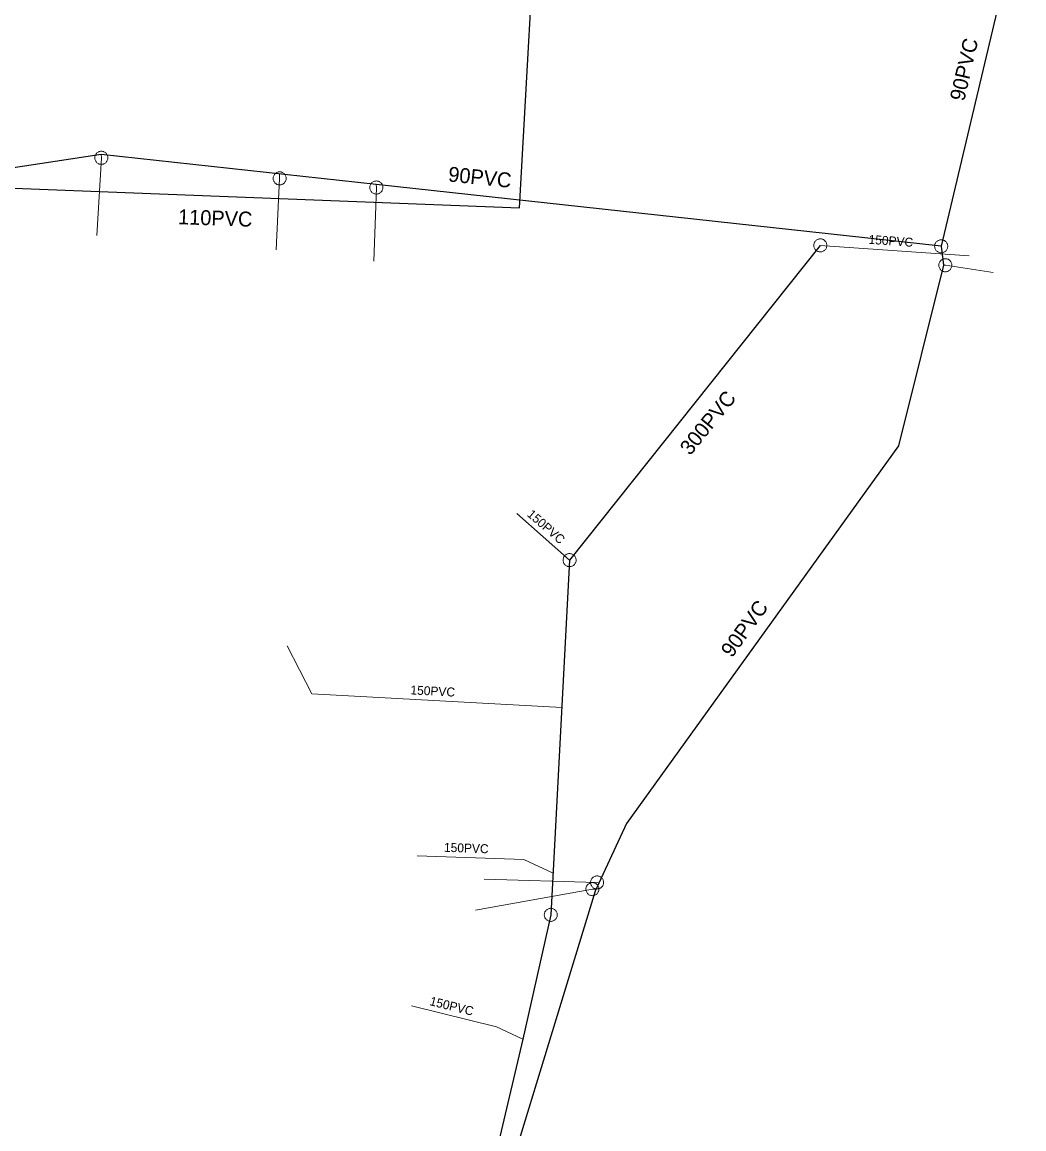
# Model space of a CAD drawing. Extents: x -741806 to -738704, y -1059275 to -1055387.
# Drawn here: x -740667.8 to -740600.7, y -1057651.1 to -1057576.9 of the extents above; entities that cross this region are included whole.
import ezdxf

# ---------------------------------------------------------------- set-up
doc = ezdxf.new("R2010")
doc.units = 0
doc.header["$LTSCALE"] = 0.4
for name, color, linetype, lineweight in [('2', 7, 'Continuous', 25), ('21', 7, 'Continuous', 13), ('3', 7, 'Continuous', 13), ('51', 7, 'Continuous', 13), ('52', 7, 'Continuous', 25), ('56', 7, 'Continuous', 13)]:
    doc.layers.add(name, color=color, linetype=linetype, lineweight=lineweight)
for name, color, linetype in [('5', 7, 'Continuous'), ('53', 7, 'Continuous'), ('55', 7, 'Continuous')]:
    doc.layers.add(name, color=color, linetype=linetype)

msp = doc.modelspace()

# ---------------------------------------------------------------- linework, layer by layer
at = {"layer": '2'}
for points in [[(-740702.59, -1057629.575), (-740677.195, -1057630.344), (-740674.756, -1057596.152), (-740674.105, -1057587.855), (-740634.449, -1057589.387), (-740633.142, -1057565.869)], [(-740614.3, -1057591.909), (-740631.1, -1057613), (-740632.359, -1057636.77), (-740634.23, -1057645.105), (-740637.395, -1057658.567), (-740638.78, -1057664.69), (-740636.789, -1057669.73), (-740646.329, -1057707.36), (-740651.609, -1057710.669)]]:
    msp.add_lwpolyline(points, dxfattribs=at)
at = {"layer": '21'}
for points in [[(-740662.486, -1057585.823), (-740662.48, -1057586.04), (-740662.782, -1057591.249)], [(-740650.542, -1057587.127), (-740650.53, -1057587.419), (-740650.767, -1057592.213)], [(-740644.067, -1057587.834), (-740644.05, -1057588.03), (-740644.224, -1057592.965)], [(-740606.041, -1057593.243), (-740605.92, -1057593.24), (-740602.725, -1057593.729)], [(-740629.138, -1057634.655), (-740629.26, -1057634.6), (-740636.829, -1057634.37)], [(-740629.339, -1057635.057), (-740629.57, -1057635.05), (-740637.417, -1057636.446)]]:
    msp.add_lwpolyline(points, dxfattribs=at)
at = {"layer": '3'}
for points in [[(-740614.736, -1057591.878), (-740614.737, -1057591.923), (-740614.733, -1057591.968), (-740614.724, -1057592.014), (-740614.711, -1057592.057), (-740614.693, -1057592.099), (-740614.67, -1057592.14), (-740614.644, -1057592.177), (-740614.614, -1057592.212), (-740614.58, -1057592.242), (-740614.544, -1057592.27), (-740614.505, -1057592.294), (-740614.463, -1057592.314), (-740614.42, -1057592.328), (-740614.376, -1057592.339), (-740614.33, -1057592.344), (-740614.284, -1057592.345), (-740614.238, -1057592.34), (-740614.194, -1057592.332), (-740614.15, -1057592.318), (-740614.107, -1057592.3), (-740614.068, -1057592.278), (-740614.031, -1057592.252), (-740613.995, -1057592.222), (-740613.964, -1057592.189), (-740613.936, -1057592.152), (-740613.914, -1057592.112), (-740613.894, -1057592.072), (-740613.879, -1057592.027), (-740613.869, -1057591.983), (-740613.863, -1057591.937), (-740613.862, -1057591.892), (-740613.866, -1057591.847), (-740613.875, -1057591.801), (-740613.889, -1057591.757), (-740613.906, -1057591.716), (-740613.928, -1057591.675), (-740613.955, -1057591.638), (-740613.986, -1057591.603), (-740614.019, -1057591.573), (-740614.055, -1057591.545), (-740614.094, -1057591.521), (-740614.136, -1057591.501), (-740614.179, -1057591.486), (-740614.223, -1057591.476), (-740614.269, -1057591.471), (-740614.315, -1057591.47), (-740614.36, -1057591.474), (-740614.405, -1057591.483), (-740614.449, -1057591.497), (-740614.492, -1057591.515), (-740614.531, -1057591.537), (-740614.569, -1057591.562), (-740614.603, -1057591.593), (-740614.635, -1057591.626), (-740614.662, -1057591.663), (-740614.686, -1057591.703), (-740614.705, -1057591.743), (-740614.72, -1057591.788), (-740614.73, -1057591.832), (-740614.736, -1057591.877)], [(-740630.771, -1057613.29), (-740630.744, -1057613.254), (-740630.719, -1057613.215), (-740630.699, -1057613.174), (-740630.683, -1057613.132), (-740630.671, -1057613.087), (-740630.664, -1057613.041), (-740630.663, -1057612.996), (-740630.665, -1057612.95), (-740630.674, -1057612.905), (-740630.686, -1057612.861), (-740630.702, -1057612.818), (-740630.723, -1057612.777), (-740630.749, -1057612.74), (-740630.778, -1057612.704), (-740630.811, -1057612.672), (-740630.847, -1057612.643), (-740630.886, -1057612.619), (-740630.926, -1057612.599), (-740630.969, -1057612.583), (-740631.014, -1057612.572), (-740631.059, -1057612.565), (-740631.104, -1057612.563), (-740631.15, -1057612.566), (-740631.195, -1057612.573), (-740631.24, -1057612.586), (-740631.282, -1057612.603), (-740631.323, -1057612.623), (-740631.361, -1057612.649), (-740631.396, -1057612.678), (-740631.428, -1057612.712), (-740631.457, -1057612.747), (-740631.481, -1057612.785), (-740631.502, -1057612.827), (-740631.517, -1057612.87), (-740631.529, -1057612.913), (-740631.536, -1057612.959), (-740631.537, -1057613.005), (-740631.534, -1057613.051), (-740631.527, -1057613.095), (-740631.515, -1057613.139), (-740631.498, -1057613.182), (-740631.477, -1057613.223), (-740631.452, -1057613.261), (-740631.423, -1057613.296), (-740631.389, -1057613.328), (-740631.354, -1057613.357), (-740631.315, -1057613.382), (-740631.274, -1057613.402), (-740631.231, -1057613.418), (-740631.186, -1057613.429), (-740631.141, -1057613.435), (-740631.096, -1057613.438), (-740631.05, -1057613.435), (-740631.005, -1057613.428), (-740630.96, -1057613.415), (-740630.918, -1057613.398), (-740630.878, -1057613.377), (-740630.839, -1057613.351), (-740630.804, -1057613.322), (-740630.772, -1057613.29)], [(-740632.382, -1057637.207), (-740632.337, -1057637.206), (-740632.292, -1057637.202), (-740632.246, -1057637.192), (-740632.203, -1057637.178), (-740632.161, -1057637.159), (-740632.121, -1057637.137), (-740632.085, -1057637.109), (-740632.05, -1057637.079), (-740632.02, -1057637.045), (-740631.993, -1057637.008), (-740631.97, -1057636.968), (-740631.951, -1057636.926), (-740631.937, -1057636.883), (-740631.927, -1057636.838), (-740631.923, -1057636.793), (-740631.922, -1057636.747), (-740631.928, -1057636.701), (-740631.936, -1057636.657), (-740631.951, -1057636.613), (-740631.97, -1057636.571), (-740631.993, -1057636.532), (-740632.019, -1057636.495), (-740632.05, -1057636.46), (-740632.084, -1057636.43), (-740632.121, -1057636.403), (-740632.161, -1057636.38), (-740632.202, -1057636.361), (-740632.246, -1057636.347), (-740632.291, -1057636.337), (-740632.337, -1057636.333), (-740632.382, -1057636.333), (-740632.427, -1057636.337), (-740632.473, -1057636.347), (-740632.517, -1057636.362), (-740632.558, -1057636.379), (-740632.598, -1057636.402), (-740632.634, -1057636.429), (-740632.669, -1057636.461), (-740632.699, -1057636.494), (-740632.726, -1057636.531), (-740632.749, -1057636.571), (-740632.768, -1057636.613), (-740632.783, -1057636.656), (-740632.792, -1057636.7), (-740632.796, -1057636.746), (-740632.797, -1057636.792), (-740632.792, -1057636.838), (-740632.783, -1057636.882), (-740632.768, -1057636.926), (-740632.749, -1057636.968), (-740632.726, -1057637.007), (-740632.7, -1057637.045), (-740632.669, -1057637.079), (-740632.635, -1057637.109), (-740632.598, -1057637.136), (-740632.558, -1057637.159), (-740632.517, -1057637.178), (-740632.473, -1057637.192), (-740632.428, -1057637.201), (-740632.383, -1057637.207)]]:
    msp.add_lwpolyline(points, dxfattribs=at)
at = {"layer": '51'}
for points in [[(-740662.043, -1057586.04), (-740662.044, -1057585.995), (-740662.052, -1057585.95), (-740662.064, -1057585.905), (-740662.08, -1057585.863), (-740662.101, -1057585.822), (-740662.125, -1057585.783), (-740662.155, -1057585.748), (-740662.187, -1057585.715), (-740662.223, -1057585.687), (-740662.261, -1057585.662), (-740662.302, -1057585.641), (-740662.345, -1057585.624), (-740662.389, -1057585.612), (-740662.434, -1057585.605), (-740662.48, -1057585.603), (-740662.526, -1057585.605), (-740662.571, -1057585.612), (-740662.615, -1057585.624), (-740662.657, -1057585.641), (-740662.699, -1057585.662), (-740662.737, -1057585.687), (-740662.772, -1057585.715), (-740662.804, -1057585.748), (-740662.834, -1057585.783), (-740662.858, -1057585.822), (-740662.88, -1057585.863), (-740662.896, -1057585.905), (-740662.907, -1057585.95), (-740662.915, -1057585.995), (-740662.918, -1057586.041), (-740662.915, -1057586.086), (-740662.907, -1057586.131), (-740662.896, -1057586.176), (-740662.88, -1057586.218), (-740662.858, -1057586.259), (-740662.834, -1057586.298), (-740662.804, -1057586.333), (-740662.772, -1057586.366), (-740662.737, -1057586.394), (-740662.699, -1057586.419), (-740662.657, -1057586.44), (-740662.615, -1057586.457), (-740662.571, -1057586.468), (-740662.526, -1057586.476), (-740662.48, -1057586.478), (-740662.434, -1057586.476), (-740662.389, -1057586.468), (-740662.345, -1057586.457), (-740662.302, -1057586.44), (-740662.261, -1057586.419), (-740662.223, -1057586.394), (-740662.187, -1057586.366), (-740662.155, -1057586.333), (-740662.125, -1057586.298), (-740662.101, -1057586.259), (-740662.08, -1057586.218), (-740662.064, -1057586.176), (-740662.052, -1057586.131), (-740662.044, -1057586.086), (-740662.043, -1057586.041)], [(-740650.093, -1057587.419), (-740650.095, -1057587.374), (-740650.102, -1057587.329), (-740650.114, -1057587.284), (-740650.13, -1057587.242), (-740650.151, -1057587.201), (-740650.176, -1057587.162), (-740650.205, -1057587.127), (-740650.237, -1057587.094), (-740650.273, -1057587.066), (-740650.311, -1057587.041), (-740650.352, -1057587.02), (-740650.395, -1057587.003), (-740650.439, -1057586.991), (-740650.484, -1057586.984), (-740650.53, -1057586.982), (-740650.576, -1057586.984), (-740650.621, -1057586.991), (-740650.665, -1057587.003), (-740650.708, -1057587.02), (-740650.749, -1057587.041), (-740650.787, -1057587.066), (-740650.823, -1057587.094), (-740650.855, -1057587.127), (-740650.884, -1057587.162), (-740650.909, -1057587.201), (-740650.93, -1057587.242), (-740650.946, -1057587.284), (-740650.958, -1057587.329), (-740650.965, -1057587.374), (-740650.968, -1057587.42), (-740650.965, -1057587.465), (-740650.958, -1057587.51), (-740650.946, -1057587.555), (-740650.93, -1057587.597), (-740650.909, -1057587.638), (-740650.884, -1057587.677), (-740650.855, -1057587.712), (-740650.823, -1057587.745), (-740650.787, -1057587.773), (-740650.749, -1057587.798), (-740650.708, -1057587.819), (-740650.665, -1057587.836), (-740650.621, -1057587.847), (-740650.576, -1057587.855), (-740650.53, -1057587.857), (-740650.484, -1057587.855), (-740650.439, -1057587.847), (-740650.395, -1057587.836), (-740650.352, -1057587.819), (-740650.311, -1057587.798), (-740650.273, -1057587.773), (-740650.237, -1057587.745), (-740650.205, -1057587.712), (-740650.176, -1057587.677), (-740650.151, -1057587.638), (-740650.13, -1057587.597), (-740650.114, -1057587.555), (-740650.102, -1057587.51), (-740650.095, -1057587.465), (-740650.093, -1057587.42)], [(-740643.613, -1057588.03), (-740643.615, -1057587.985), (-740643.622, -1057587.94), (-740643.634, -1057587.895), (-740643.65, -1057587.853), (-740643.671, -1057587.812), (-740643.696, -1057587.773), (-740643.725, -1057587.738), (-740643.757, -1057587.705), (-740643.793, -1057587.677), (-740643.831, -1057587.652), (-740643.872, -1057587.631), (-740643.915, -1057587.614), (-740643.959, -1057587.602), (-740644.004, -1057587.595), (-740644.05, -1057587.593), (-740644.096, -1057587.595), (-740644.141, -1057587.602), (-740644.185, -1057587.614), (-740644.228, -1057587.631), (-740644.269, -1057587.652), (-740644.307, -1057587.677), (-740644.343, -1057587.705), (-740644.375, -1057587.738), (-740644.404, -1057587.773), (-740644.429, -1057587.812), (-740644.45, -1057587.853), (-740644.466, -1057587.895), (-740644.478, -1057587.94), (-740644.485, -1057587.985), (-740644.488, -1057588.031), (-740644.485, -1057588.076), (-740644.478, -1057588.121), (-740644.466, -1057588.166), (-740644.45, -1057588.208), (-740644.429, -1057588.249), (-740644.404, -1057588.288), (-740644.375, -1057588.323), (-740644.343, -1057588.356), (-740644.307, -1057588.384), (-740644.269, -1057588.409), (-740644.228, -1057588.43), (-740644.185, -1057588.447), (-740644.141, -1057588.458), (-740644.096, -1057588.466), (-740644.05, -1057588.468), (-740644.004, -1057588.466), (-740643.959, -1057588.458), (-740643.915, -1057588.447), (-740643.872, -1057588.43), (-740643.831, -1057588.409), (-740643.793, -1057588.384), (-740643.757, -1057588.356), (-740643.725, -1057588.323), (-740643.696, -1057588.288), (-740643.671, -1057588.249), (-740643.65, -1057588.208), (-740643.634, -1057588.166), (-740643.622, -1057588.121), (-740643.615, -1057588.076), (-740643.613, -1057588.031)], [(-740605.762, -1057591.97), (-740605.764, -1057591.925), (-740605.771, -1057591.88), (-740605.783, -1057591.835), (-740605.799, -1057591.793), (-740605.82, -1057591.752), (-740605.845, -1057591.713), (-740605.874, -1057591.678), (-740605.906, -1057591.645), (-740605.942, -1057591.617), (-740605.98, -1057591.592), (-740606.021, -1057591.571), (-740606.064, -1057591.554), (-740606.108, -1057591.542), (-740606.153, -1057591.535), (-740606.199, -1057591.533), (-740606.245, -1057591.535), (-740606.29, -1057591.542), (-740606.334, -1057591.554), (-740606.377, -1057591.571), (-740606.418, -1057591.592), (-740606.456, -1057591.617), (-740606.492, -1057591.645), (-740606.524, -1057591.678), (-740606.553, -1057591.713), (-740606.578, -1057591.752), (-740606.599, -1057591.793), (-740606.615, -1057591.835), (-740606.627, -1057591.88), (-740606.634, -1057591.925), (-740606.637, -1057591.971), (-740606.634, -1057592.016), (-740606.627, -1057592.061), (-740606.615, -1057592.106), (-740606.599, -1057592.148), (-740606.578, -1057592.189), (-740606.553, -1057592.228), (-740606.524, -1057592.263), (-740606.492, -1057592.296), (-740606.456, -1057592.324), (-740606.418, -1057592.349), (-740606.377, -1057592.37), (-740606.334, -1057592.387), (-740606.29, -1057592.398), (-740606.245, -1057592.406), (-740606.199, -1057592.408), (-740606.153, -1057592.406), (-740606.108, -1057592.398), (-740606.064, -1057592.387), (-740606.021, -1057592.37), (-740605.98, -1057592.349), (-740605.942, -1057592.324), (-740605.906, -1057592.296), (-740605.874, -1057592.263), (-740605.845, -1057592.228), (-740605.82, -1057592.189), (-740605.799, -1057592.148), (-740605.783, -1057592.106), (-740605.771, -1057592.061), (-740605.764, -1057592.016), (-740605.762, -1057591.971)], [(-740605.483, -1057593.24), (-740605.485, -1057593.195), (-740605.492, -1057593.15), (-740605.504, -1057593.105), (-740605.52, -1057593.063), (-740605.541, -1057593.022), (-740605.566, -1057592.983), (-740605.595, -1057592.948), (-740605.627, -1057592.915), (-740605.663, -1057592.887), (-740605.701, -1057592.862), (-740605.742, -1057592.841), (-740605.785, -1057592.824), (-740605.829, -1057592.812), (-740605.874, -1057592.805), (-740605.92, -1057592.803), (-740605.966, -1057592.805), (-740606.011, -1057592.812), (-740606.055, -1057592.824), (-740606.098, -1057592.841), (-740606.139, -1057592.862), (-740606.177, -1057592.887), (-740606.213, -1057592.915), (-740606.245, -1057592.948), (-740606.274, -1057592.983), (-740606.299, -1057593.022), (-740606.32, -1057593.063), (-740606.336, -1057593.105), (-740606.348, -1057593.15), (-740606.355, -1057593.195), (-740606.358, -1057593.241), (-740606.355, -1057593.286), (-740606.348, -1057593.331), (-740606.336, -1057593.376), (-740606.32, -1057593.418), (-740606.299, -1057593.459), (-740606.274, -1057593.498), (-740606.245, -1057593.533), (-740606.213, -1057593.566), (-740606.177, -1057593.594), (-740606.139, -1057593.619), (-740606.098, -1057593.64), (-740606.055, -1057593.657), (-740606.011, -1057593.668), (-740605.966, -1057593.676), (-740605.92, -1057593.678), (-740605.874, -1057593.676), (-740605.829, -1057593.668), (-740605.785, -1057593.657), (-740605.742, -1057593.64), (-740605.701, -1057593.619), (-740605.663, -1057593.594), (-740605.627, -1057593.566), (-740605.595, -1057593.533), (-740605.566, -1057593.498), (-740605.541, -1057593.459), (-740605.52, -1057593.418), (-740605.504, -1057593.376), (-740605.492, -1057593.331), (-740605.485, -1057593.286), (-740605.483, -1057593.241)], [(-740630.006, -1057635.034), (-740630.006, -1057635.079), (-740630, -1057635.124), (-740629.99, -1057635.17), (-740629.975, -1057635.212), (-740629.956, -1057635.254), (-740629.932, -1057635.294), (-740629.904, -1057635.33), (-740629.873, -1057635.364), (-740629.838, -1057635.393), (-740629.801, -1057635.419), (-740629.761, -1057635.442), (-740629.718, -1057635.46), (-740629.675, -1057635.474), (-740629.63, -1057635.482), (-740629.584, -1057635.486), (-740629.538, -1057635.485), (-740629.493, -1057635.48), (-740629.449, -1057635.469), (-740629.405, -1057635.454), (-740629.363, -1057635.434), (-740629.325, -1057635.41), (-740629.288, -1057635.384), (-740629.255, -1057635.352), (-740629.224, -1057635.318), (-740629.198, -1057635.28), (-740629.176, -1057635.239), (-740629.158, -1057635.198), (-740629.145, -1057635.153), (-740629.136, -1057635.109), (-740629.132, -1057635.063), (-740629.133, -1057635.018), (-740629.139, -1057634.973), (-740629.149, -1057634.927), (-740629.164, -1057634.885), (-740629.183, -1057634.843), (-740629.207, -1057634.803), (-740629.235, -1057634.767), (-740629.266, -1057634.733), (-740629.301, -1057634.704), (-740629.338, -1057634.678), (-740629.378, -1057634.655), (-740629.42, -1057634.637), (-740629.464, -1057634.624), (-740629.509, -1057634.615), (-740629.555, -1057634.611), (-740629.601, -1057634.612), (-740629.646, -1057634.618), (-740629.69, -1057634.628), (-740629.734, -1057634.643), (-740629.776, -1057634.663), (-740629.814, -1057634.687), (-740629.851, -1057634.713), (-740629.884, -1057634.745), (-740629.915, -1057634.779), (-740629.941, -1057634.817), (-740629.963, -1057634.858), (-740629.981, -1057634.899), (-740629.994, -1057634.944), (-740630.003, -1057634.988), (-740630.006, -1057635.033)], [(-740629.658, -1057634.419), (-740629.674, -1057634.461), (-740629.686, -1057634.505), (-740629.694, -1057634.551), (-740629.697, -1057634.596), (-740629.694, -1057634.642), (-740629.688, -1057634.688), (-740629.676, -1057634.732), (-740629.66, -1057634.775), (-740629.639, -1057634.815), (-740629.614, -1057634.854), (-740629.586, -1057634.89), (-740629.553, -1057634.923), (-740629.518, -1057634.952), (-740629.48, -1057634.977), (-740629.439, -1057634.997), (-740629.396, -1057635.015), (-740629.352, -1057635.027), (-740629.307, -1057635.034), (-740629.261, -1057635.036), (-740629.215, -1057635.034), (-740629.17, -1057635.026), (-740629.126, -1057635.016), (-740629.083, -1057634.999), (-740629.042, -1057634.979), (-740629.003, -1057634.954), (-740628.967, -1057634.925), (-740628.936, -1057634.893), (-740628.906, -1057634.857), (-740628.881, -1057634.819), (-740628.86, -1057634.778), (-740628.844, -1057634.736), (-740628.832, -1057634.692), (-740628.824, -1057634.646), (-740628.821, -1057634.601), (-740628.824, -1057634.555), (-740628.831, -1057634.509), (-740628.843, -1057634.466), (-740628.858, -1057634.422), (-740628.88, -1057634.382), (-740628.904, -1057634.344), (-740628.933, -1057634.308), (-740628.965, -1057634.274), (-740629, -1057634.246), (-740629.038, -1057634.22), (-740629.079, -1057634.2), (-740629.122, -1057634.183), (-740629.166, -1057634.171), (-740629.211, -1057634.163), (-740629.257, -1057634.161), (-740629.303, -1057634.164), (-740629.348, -1057634.171), (-740629.392, -1057634.181), (-740629.435, -1057634.198), (-740629.476, -1057634.218), (-740629.515, -1057634.244), (-740629.551, -1057634.272), (-740629.583, -1057634.304), (-740629.612, -1057634.34), (-740629.637, -1057634.378), (-740629.657, -1057634.419)]]:
    msp.add_lwpolyline(points, dxfattribs=at)
at = {"layer": '52'}
msp.add_line((-740600.658, -1057568.607), (-740606.199, -1057591.97), dxfattribs=at)
for points in [[(-740606.199, -1057591.97), (-740644.067, -1057587.834), (-740662.486, -1057585.823), (-740681.293, -1057588.681), (-740688.844, -1057587.905), (-740723.829, -1057584.519)], [(-740606.199, -1057591.97), (-740606.041, -1057593.243), (-740609.05, -1057605.335), (-740627.287, -1057630.651), (-740629.138, -1057634.655), (-740629.397, -1057635.175), (-740635.155, -1057654.047), (-740638.329, -1057666.617), (-740642.039, -1057681.06)]]:
    msp.add_lwpolyline(points, dxfattribs=at)
at = {"layer": '56'}
for p, q in [((-740604.316, -1057592.604), (-740614.3, -1057591.909)), ((-740634.633, -1057609.885), (-740631.1, -1057613))]:
    msp.add_line(p, q, dxfattribs=at)
for points in [[(-740650.037, -1057618.742), (-740648.373, -1057621.96), (-740631.624, -1057622.887)], [(-740641.313, -1057632.81), (-740634.166, -1057633.068), (-740632.212, -1057633.984)], [(-740641.695, -1057642.862), (-740636.008, -1057644.284), (-740634.23, -1057645.105)]]:
    msp.add_lwpolyline(points, dxfattribs=at)

# ---------------------------------------------------------------- texts
at = {"layer": '5'}
for s, rotation, p in [('110PVC', 358, (-740657.351, -1057590.488)), ('300PVC', 51, (-740623.016, -1057606.038))]:
    msp.add_text(s, height=1, rotation=rotation, dxfattribs=at).set_placement(p)
at = {"layer": '53'}
for rotation, p in [(77, (-740604.659, -1057582.292)), (354, (-740639.27, -1057587.617)), (54, (-740620.226, -1057619.591))]:
    msp.add_text('90PVC ', height=1, rotation=rotation, dxfattribs=at).set_placement(p)
at = {"layer": '55'}
for rotation, p in [(356, (-740611.08, -1057591.801)), (319, (-740633.997, -1057610.003)), (357, (-740641.776, -1057621.994)), (358, (-740639.526, -1057632.542)), (346, (-740640.518, -1057642.815))]:
    msp.add_text('150PVC', height=0.6, rotation=rotation, dxfattribs=at).set_placement(p)

doc.saveas('drawing.dxf')
